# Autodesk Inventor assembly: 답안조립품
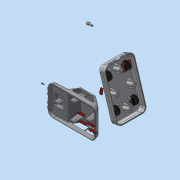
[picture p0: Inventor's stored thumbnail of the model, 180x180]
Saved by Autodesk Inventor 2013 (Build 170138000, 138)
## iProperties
Created: 2015-05
Part Number: 답안조립품
Document SubType Name: Assembly
Designer: Administrator
Author: Administrator
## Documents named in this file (7)
- C:\Users\Administrator\Desktop\450508V1050\답안조립품.iam
- C:\Users\Administrator\Desktop\450508V1050\본체.ipt
- C:\Users\Administrator\Desktop\450508V1050\M2x4.ipt
- C:\Users\Administrator\Desktop\450508V1050\M4x10.ipt
- C:\Users\Administrator\Desktop\450508V1050\바퀴.ipt
- C:\Users\Administrator\Desktop\450508V1050\바퀴고정부.ipt
- C:\Users\Administrator\Desktop\450508V1050\커버.ipt
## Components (2 placed, 2 different names)
1. M2x4:1
2. M4x10:1
